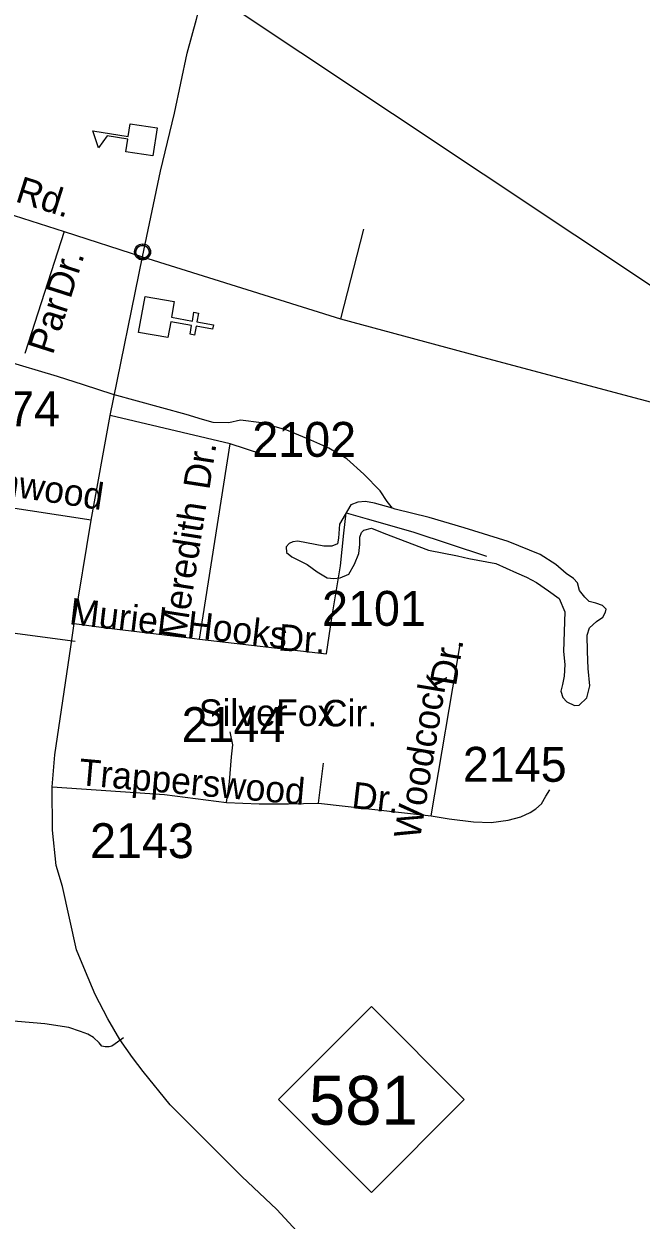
# Model space of a CAD drawing. Extents: x 2260773 to 2342389, y 552869 to 618546.
# Drawn here: x 2276429 to 2278640, y 603238 to 607521 of the extents above; entities that cross this region are included whole.
import ezdxf

# ---------------------------------------------------------------- set-up
doc = ezdxf.new("R2010")
doc.units = 0
for name, color, linetype in [('Exist Civil Demographics Community CELL', 7, 'Continuous'), ('Exist Cultural Church CELL', 7, 'Continuous'), ('Exist Cultural Educational Facility High CELL', 7, 'Continuous'), ('Exist Hydrographic Misc Water Feature', 7, 'Continuous'), ('Exist Railroad Mainline', 7, 'Continuous'), ('Exist Road Non-System Type 51', 7, 'Continuous'), ('Exist Road Non-System Type 51 Label', 7, 'Continuous'), ('Exist Road Primary NC Attributed', 7, 'Continuous'), ('Exist Road Primary NC Shield CELL', 7, 'Continuous'), ('Exist Road Primary NC Shield Number Label', 7, 'Continuous'), ('Exist Road Secondary Type 51 Attributed', 7, 'Continuous'), ('Exist Road Secondary Type 51 Label', 7, 'Continuous'), ('Exist Road Secondary Type 51 Number Label', 7, 'Continuous')]:
    doc.layers.add(name, color=color, linetype=linetype)

msp = doc.modelspace()

# ---------------------------------------------------------------- linework, layer by layer
at = {"layer": 'Exist Civil Demographics Community CELL'}
msp.add_lwpolyline([(2276830.1, 606708), (2276830.4, 606709.7), (2276830.9, 606711.7), (2276831.8, 606713.9), (2276832.7, 606715.6), (2276833.7, 606717.4), (2276834.9, 606718.9), (2276836.1, 606720.3), (2276837.5, 606721.7), (2276839.1, 606723.1), (2276840.8, 606724.2), (2276842.3, 606725), (2276843.8, 606725.8), (2276845.5, 606726.5), (2276847.2, 606727), (2276848.5, 606727.4), (2276850, 606727.6), (2276851.3, 606727.8), (2276853.2, 606727.9), (2276854.6, 606727.9), (2276856.3, 606727.8), (2276857.8, 606727.6), (2276859.3, 606727.3), (2276860.8, 606726.9), (2276862.4, 606726.3), (2276864.4, 606725.4), (2276866.3, 606724.3), (2276867.9, 606723.2), (2276869.4, 606722), (2276870.4, 606721.1), (2276871.7, 606719.7), (2276872.9, 606718.3), (2276873.8, 606716.9), (2276874.8, 606715.4), (2276875.5, 606713.8), (2276876.1, 606712.3), (2276876.6, 606710.7), (2276877, 606709.3), (2276877.3, 606707.5), (2276877.5, 606706.1), (2276877.6, 606704.2), (2276877.5, 606702.5), (2276877.4, 606700.7), (2276877.1, 606699.1), (2276876.6, 606697.2), (2276876, 606695.4), (2276875.3, 606693.9), (2276874.4, 606692), (2276873.3, 606690.4), (2276872.3, 606689), (2276871, 606687.5), (2276869.4, 606686), (2276867.9, 606684.8), (2276866.3, 606683.7), (2276865, 606682.9), (2276862.9, 606682), (2276860.8, 606681.1), (2276859, 606680.7), (2276856.9, 606680.3), (2276855.6, 606680.1), (2276854.2, 606680.1), (2276852.5, 606680.1), (2276851.2, 606680.2), (2276849.5, 606680.4), (2276847.7, 606680.8), (2276846.3, 606681.2), (2276844.7, 606681.8), (2276843.3, 606682.4), (2276842.1, 606683.1), (2276840.1, 606684.3), (2276838.4, 606685.6), (2276836.9, 606687), (2276835.5, 606688.5), (2276834.5, 606689.7), (2276833.6, 606690.9), (2276832.4, 606693.1), (2276831.8, 606694.2), (2276831.3, 606695.4), (2276830.5, 606697.9), (2276830.1, 606700.1), (2276829.9, 606701.6), (2276829.8, 606703.6), (2276829.7, 606705), (2276829.9, 606707)], close=True, dxfattribs=at)
msp.add_lwpolyline([(2276830.1, 606708), (2276830.4, 606709.7), (2276830.9, 606711.7), (2276831.8, 606713.9), (2276832.7, 606715.6), (2276833.7, 606717.4), (2276834.9, 606718.9), (2276836.1, 606720.3), (2276837.5, 606721.7), (2276839.1, 606723.1), (2276840.8, 606724.2), (2276842.3, 606725), (2276843.8, 606725.8), (2276845.5, 606726.5), (2276847.2, 606727), (2276848.5, 606727.4), (2276850, 606727.6), (2276851.3, 606727.8), (2276853.2, 606727.9), (2276854.6, 606727.9), (2276856.3, 606727.8), (2276857.8, 606727.6), (2276859.3, 606727.3), (2276860.8, 606726.9), (2276862.4, 606726.3), (2276864.4, 606725.4), (2276866.3, 606724.3), (2276867.9, 606723.2), (2276869.4, 606722), (2276870.4, 606721.1), (2276871.7, 606719.7), (2276872.9, 606718.3), (2276873.8, 606716.9), (2276874.8, 606715.4), (2276875.5, 606713.8), (2276876.1, 606712.3), (2276876.6, 606710.7), (2276877, 606709.3), (2276877.3, 606707.5), (2276877.5, 606706.1), (2276877.6, 606704.2), (2276877.5, 606702.5), (2276877.4, 606700.7), (2276877.1, 606699.1), (2276876.6, 606697.2), (2276876, 606695.4), (2276875.3, 606693.9), (2276874.4, 606692), (2276873.3, 606690.4), (2276872.3, 606689), (2276871, 606687.5), (2276869.4, 606686), (2276867.9, 606684.8), (2276866.3, 606683.7), (2276865, 606682.9), (2276862.9, 606682), (2276860.8, 606681.1), (2276859, 606680.7), (2276856.9, 606680.3), (2276855.6, 606680.1), (2276854.2, 606680.1), (2276852.5, 606680.1), (2276851.2, 606680.2), (2276849.5, 606680.4), (2276847.7, 606680.8), (2276846.3, 606681.2), (2276844.7, 606681.8), (2276843.3, 606682.4), (2276842.1, 606683.1), (2276840.1, 606684.3), (2276838.4, 606685.6), (2276836.9, 606687), (2276835.5, 606688.5), (2276834.5, 606689.7), (2276833.6, 606690.9), (2276832.4, 606693.1), (2276831.8, 606694.2), (2276831.3, 606695.4), (2276830.5, 606697.9), (2276830.1, 606700.1), (2276829.9, 606701.6), (2276829.8, 606703.6), (2276829.7, 606705), (2276829.9, 606707)], close=True, dxfattribs=at)
for centre, radius in [((2276853.7, 606704.2), 28.8), ((2276853.7, 606704.2), 28.8), ((2276853.6, 606704.3), 23.4), ((2276853.6, 606704.3), 23.4)]:
    msp.add_circle(centre, radius, dxfattribs=at)
at = {"layer": 'Exist Cultural Church CELL'}
msp.add_lwpolyline([(2276967.3, 606526.3), (2276957.4, 606470.3), (2277032.3, 606456.9), (2277038, 606488.4), (2277053.7, 606485.6), (2277048.1, 606454.1), (2277107.3, 606443.5), (2277104.5, 606427.8), (2277045.3, 606438.3), (2277039.6, 606406.8), (2277023.9, 606409.6), (2277029.5, 606441.1), (2276954.6, 606454.5), (2276944.3, 606397.7), (2276839.5, 606416.4), (2276862.5, 606545)], close=True, dxfattribs=at)
at = {"layer": 'Exist Cultural Educational Facility High CELL'}
msp.add_lwpolyline([(2276890.5, 607047.8), (2276793.8, 607063), (2276801, 607108.5), (2276726.8, 607120.2), (2276695.5, 607077.5), (2276675.5, 607138), (2276802.5, 607118), (2276809.6, 607163.4), (2276906.4, 607148.2)], close=True, dxfattribs=at)
at = {"layer": 'Exist Hydrographic Misc Water Feature'}
for points in [[(2277749.3, 605787.5), (2277730.6, 605811.4), (2277704.8, 605849.3), (2277646.2, 605908.5), (2277585.7, 605963.8), (2277520.9, 606001.5), (2277456.9, 606030.6), (2277370.6, 606065.9), (2277280.3, 606092.9), (2277204.1, 606102.4), (2277162.9, 606092), (2277106.5, 606093.6), (2277068.5, 606104.9), (2277010.1, 606122.3), (2276748, 606193.8), (2276641.6, 606228.9), (2276549.5, 606257.8), (2276356.8, 606316), (2276178.8, 606364.3), (2276078.3, 606397.3), (2275917.6, 606460.1), (2275791.9, 606490.8)], [(2277749.3, 605787.5), (2277684.9, 605804.8), (2277652.9, 605810.9), (2277624.8, 605808.2), (2277599.4, 605798.3), (2277559.4, 605729.7), (2277556.1, 605679.9), (2277552.4, 605659.8), (2277532.4, 605651.4), (2277502.6, 605651.5), (2277472.1, 605657.3), (2277410.3, 605668.6), (2277392.5, 605666.4), (2277378.6, 605660), (2277368.5, 605648.1), (2277369.1, 605628.2), (2277389, 605612.2), (2277443.2, 605585), (2277479.7, 605559.2), (2277515.5, 605537.6), (2277539.5, 605535.6), (2277561.5, 605537.9), (2277593.3, 605550.2), (2277613.3, 605586.5), (2277628.5, 605624.4), (2277632.2, 605656.6), (2277632.4, 605682.6), (2277637.8, 605700.4), (2277646, 605708.5), (2277673.8, 605714.9), (2277718.1, 605697.2), (2277878.5, 605637), (2277982.4, 605616), (2278022.6, 605606.4), (2278118.8, 605589), (2278193, 605555.9), (2278229.1, 605540.3), (2278265.4, 605520.7), (2278307.7, 605490.8), (2278346, 605463.5), (2278366.1, 605415.5), (2278361.6, 605273.4), (2278366.3, 605227.7), (2278364.5, 605185.8), (2278358.5, 605155.9), (2278352.8, 605131.6), (2278358.9, 605109.6), (2278373.3, 605093.6), (2278401.2, 605080.1), (2278417.4, 605082.1), (2278445, 605108.4), (2278456.7, 605150.8), (2278450, 605212.7), (2278447.5, 605274.3), (2278447.1, 605332.4), (2278454.7, 605358.3), (2278480.5, 605380.8), (2278502.5, 605397), (2278512.3, 605415), (2278514.3, 605424.8), (2278501.6, 605438.9), (2278477.8, 605446.5), (2278453.9, 605452.6), (2278437.9, 605468.4), (2278419.6, 605492.2), (2278411.4, 605519.8), (2278397.1, 605535.7), (2278370.8, 605553.5), (2278334.9, 605585.2), (2278278.3, 605620.6), (2278164.1, 605667.4), (2278005.6, 605716), (2277881.1, 605753), (2277759.1, 605783.5), (2277749.3, 605787.5)]]:
    msp.add_lwpolyline(points, dxfattribs=at)
at = {"layer": 'Exist Railroad Mainline'}
msp.add_lwpolyline([(2279466.6, 606053.8), (2278731.4, 606546.2), (2277092, 607636.3), (2277075.8, 607647)], dxfattribs=at)
at = {"layer": 'Exist Road Non-System Type 51'}
for p, q in [((2277645.7, 606785.9), (2277562.8, 606465.3)), ((2276572.4, 606777.7), (2276432.5, 606340.7)), ((2277167.3, 606017.7), (2276738.1, 606119.2)), ((2277281.5, 605980.8), (2277167.3, 606017.7)), ((2276181.9, 605368.8), (2276612.2, 605310.9))]:
    msp.add_line(p, q, dxfattribs=at)
for points in [[(2277513.2, 605265.6), (2277531.4, 605394.7), (2277562.9, 605580.2), (2277574.4, 605697.7), (2277582.7, 605770.6), (2277658.8, 605749), (2277822.6, 605702.7), (2278085.7, 605614.9)], [(2277154.5, 604733.2), (2277165.7, 604807.3), (2277172.4, 604897), (2277176.9, 604939.7), (2277167.9, 604986.8)], [(2277887.8, 604686.1), (2277951.7, 604674.6), (2278039.4, 604664.6), (2278103.1, 604661.4), (2278163.6, 604670.4), (2278208.5, 604681.6), (2278242.1, 604697.3), (2278262.3, 604710.8), (2278282.5, 604728.7), (2278298.2, 604755.7), (2278312.4, 604778.9)], [(2276785.5, 603891.2), (2276755.6, 603869.1), (2276743.9, 603860.9), (2276733.8, 603858.9), (2276719.8, 603858.8), (2276707.9, 603860.6), (2276697.7, 603872.4), (2276677.5, 603892.2), (2276657.4, 603904), (2276631.4, 603913.8), (2276589.3, 603927.4), (2276503.2, 603940.6), (2276167.1, 603969.4), (2275692.9, 604019), (2275404.8, 604046.2), (2275346.7, 604051.6), (2275312.7, 604053.3), (2275242.9, 604050.7), (2275117.1, 604043.5), (2274973, 604048.2), (2274790.9, 604070.5), (2274612.6, 604103.2)]]:
    msp.add_lwpolyline(points, dxfattribs=at)
at = {"layer": 'Exist Road Primary NC Attributed'}
msp.add_line((2276608.5, 605374.1), (2276669.5, 605743.5), dxfattribs=at)
for points in [[(2276853.2, 606686.5), (2276918.2, 606993), (2276968.2, 607201.3), (2277014.1, 607415.5), (2277047, 607537.8), (2277072, 607636.1), (2277075.8, 607647)], [(2276669.5, 605743.5), (2276738.1, 606119.2), (2276853.2, 606686.5)], [(2276530.4, 604789.3), (2276539.8, 604904.1), (2276558.7, 605033.1), (2276596.5, 605290.8), (2276608.5, 605374.1)], [(2277581.8, 603023.4), (2277464.3, 603136.8), (2277335.3, 603276.3), (2277209.7, 603394.1), (2277092.9, 603510.9), (2276952.2, 603650.9), (2276855.9, 603769.9), (2276817.4, 603820.6), (2276772.1, 603885.1), (2276728.9, 603958.7), (2276684.3, 604045.8), (2276649.2, 604128.2), (2276617.5, 604205.8), (2276566.5, 604432.9), (2276544.5, 604508), (2276531, 604634.3), (2276530.4, 604789.3)]]:
    msp.add_lwpolyline(points, dxfattribs=at)
at = {"layer": 'Exist Road Primary NC Shield CELL'}
msp.add_lwpolyline([(2277340.4, 603669.5), (2277673.4, 604002.5), (2278006.4, 603669.5), (2277673.4, 603336.5)], close=True, dxfattribs=at)
at = {"layer": 'Exist Road Secondary Type 51 Attributed'}
for p, q in [((2277058.2, 605318.4), (2277167.3, 606017.7)), ((2276669.5, 605743.5), (2276211, 605814.8)), ((2277058.2, 605318.4), (2277513.2, 605265.6)), ((2277484.1, 604731), (2277502.5, 604874.6))]:
    msp.add_line(p, q, dxfattribs=at)
for points in [[(2274125.2, 607595.5), (2275085.3, 607256.8), (2275143.8, 607237.3), (2275198.4, 607219.1), (2275233.3, 607207.4), (2275596.6, 607088.5), (2275914.8, 606983.4), (2276137.4, 606917.7), (2276364, 606843.7), (2276572.4, 606777.7), (2276853.2, 606686.5)], [(2276853.2, 606686.5), (2277562.8, 606465.3), (2278089, 606322.9), (2278636.5, 606176.6), (2278942.8, 606095.5), (2279142.5, 606042.1), (2279227.4, 606028.3), (2279286.7, 606026.3), (2279342.1, 606028.3), (2279427.1, 606040.1), (2279466.6, 606053.8)], [(2276608.5, 605374.1), (2276723.7, 605358), (2277021.8, 605322.7), (2277058.2, 605318.4)], [(2277887.8, 604686.1), (2277991.1, 605298.5)], [(2276530.4, 604789.3), (2276932.5, 604762.4), (2277154.5, 604733.2), (2277271.1, 604728.7), (2277376.5, 604728.7), (2277484.1, 604731)], [(2277484.1, 604731), (2277887.8, 604686.1)]]:
    msp.add_lwpolyline(points, dxfattribs=at)

# ---------------------------------------------------------------- texts
at = {"layer": 'Exist Road Non-System Type 51 Label'}
for s, p in [('Dr.', (2276595.2, 606533.2)), ('Par', (2276532, 606333))]:
    msp.add_text(s, height=95, rotation=72.2481, dxfattribs=at).set_placement(p)
at = {"layer": 'Exist Road Primary NC Shield Number Label'}
msp.add_text('581', height=175, dxfattribs=at).set_placement((2277449.5, 603579.8))
at = {"layer": 'Exist Road Secondary Type 51 Label'}
for s, rotation, p in [('Rd.', 342.4279, (2276393.8, 606885.9)), ('Dr.', 81.1299, (2277092.8, 605850)), ('Glenwood', 351.3912, (2276140.4, 605865.7)), ('Meredith', 81.1299, (2277006.9, 605313)), ('Muriel', 353.247, (2276588.2, 605372)), ('Hooks', 353.2822, (2277010, 605325.4)), ('Dr.', 355.7983, (2277337.4, 605278)), ('Dr.', 80.5422, (2277976.4, 605147.2)), ('Woodcock', 80.5422, (2277847.2, 604597.9)), ('Trapperswood', 354.9319, (2276622.2, 604796.1)), ('Dr.', 353.5066, (2277599.8, 604713.6))]:
    msp.add_text(s, height=95, rotation=rotation, dxfattribs=at).set_placement(p)
for s, p in [('Silver', (2277055.6, 605007.3)), ('Fox', (2277332.6, 605007.1)), ('Cir.', (2277496.7, 605005.6))]:
    msp.add_text(s, height=95, dxfattribs=at).set_placement(p)
at = {"layer": 'Exist Road Secondary Type 51 Number Label'}
for s, p in [('1274', (2276186.1, 606080.4)), ('2102', (2277246.8, 605970.7)), ('2101', (2277496.9, 605365.7)), ('2144', (2276993.6, 604949.6)), ('2145', (2278001.2, 604807.4)), ('2143', (2276665.7, 604534.1))]:
    msp.add_text(s, height=125, dxfattribs=at).set_placement(p)

doc.saveas('drawing.dxf')
